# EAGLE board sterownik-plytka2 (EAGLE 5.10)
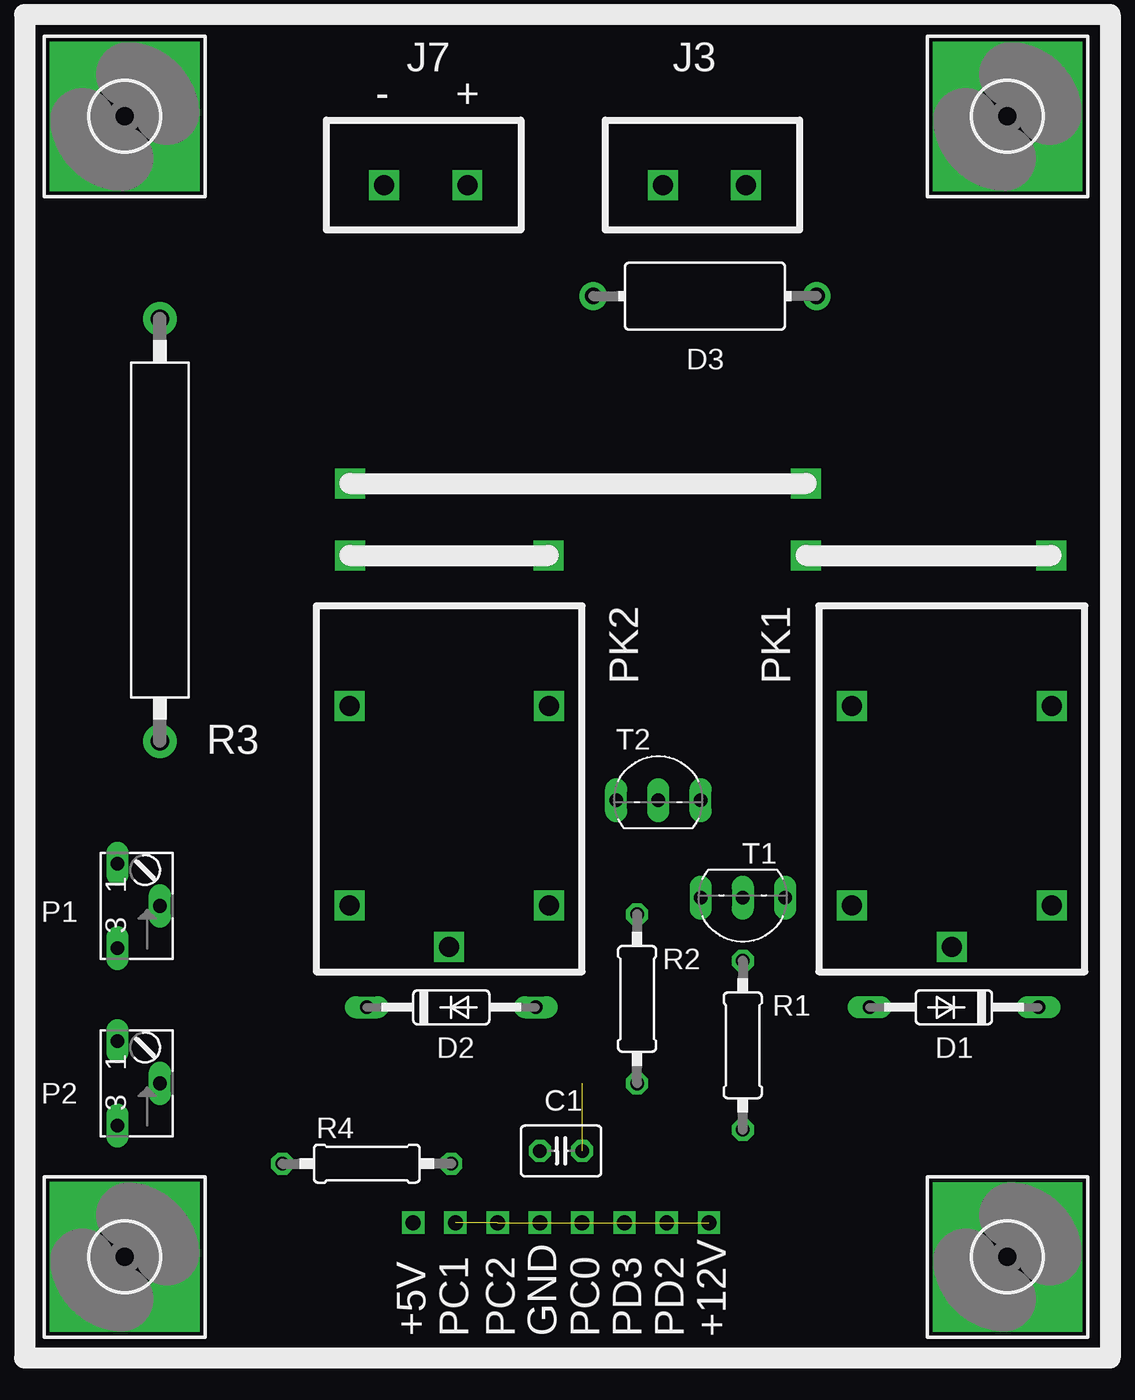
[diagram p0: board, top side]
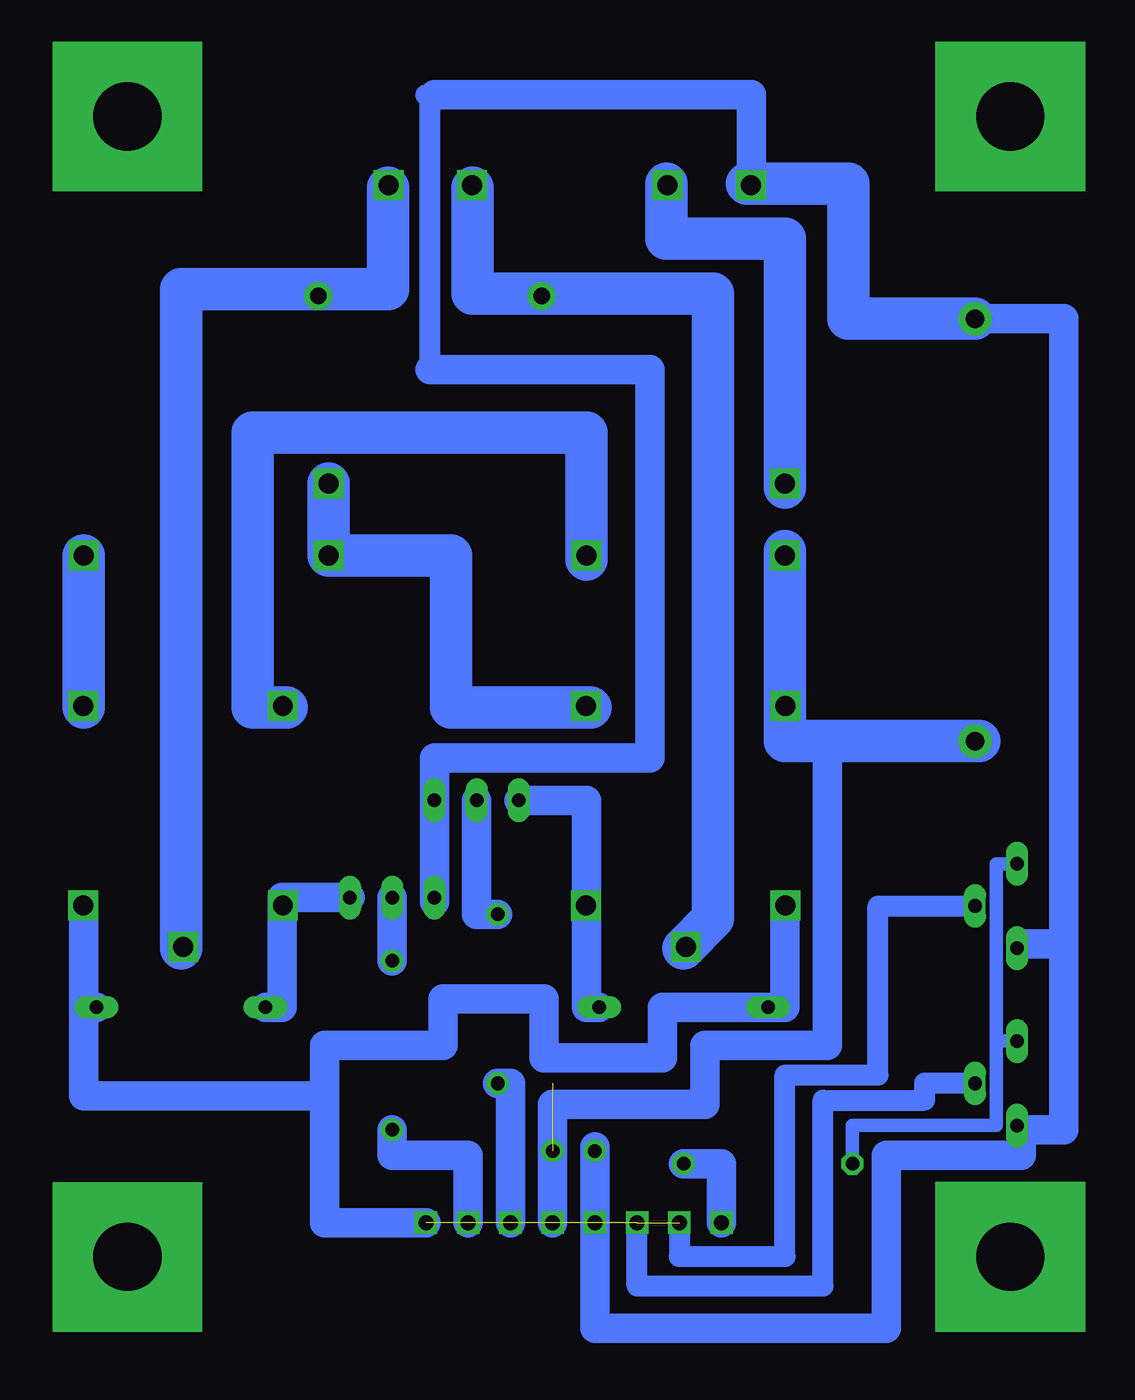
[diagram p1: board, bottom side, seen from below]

No outline drawn. Coordinates in mm, seen from the top.
Copper layers (1*16): Top 0.035mm / dielectric 1.5mm / Bottom 0.035mm
Design rules "default": minimum track width 10mil, minimum drill 24mil, track to track 8mil, track to pad 8mil, pad to pad 8mil, via to via 8mil, smd to smd 8mil, copper to edge 40mil, drill to drill 8mil, minimum pad ring 10mil, minimum via ring 8mil, stop-mask expansion 4mil, vias tented up to drill 0mil, thermal gap 10mil

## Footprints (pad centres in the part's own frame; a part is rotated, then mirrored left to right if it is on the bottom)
C025-030X050 = drill 0.813 octagon: 1 -1.27,0; 2 1.27,0
DO35-10 = drill 0.813 long: A 5.08,0; C -5.08,0
IRF-3 = drill 1 pad 1.676 round: 1 -6.705,0; 2 6.73,0
4,1-PAD-SQUARE = drill 4.1 pad 9 square: B4,1 0,0
B64W = drill 0.813 long: A 2.54,0; E -2.54,0; S 0,-2.54
0207/10 = drill 0.813 octagon: 1 -5.08,0; 2 5.08,0
CA4080 = drill 1.1 pad 2 round: 1 -12.7,0; 2 12.7,0
TO92-BCE = drill 0.813 long: B -2.54,0; C 0,0; E 2.54,0

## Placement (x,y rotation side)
C1  [C025-030X050]  32.51,12.7 180 top
D1  [DO35-10]  56.13,21.34 180 top
D2  [DO35-10]  25.91,21.34 0 top
D3  [IRF-3]  41.15,64.11 0 top
E$1  [4,1-PAD-SQUARE]  6.27,6.33 0 top
E$14  [4,1-PAD-SQUARE]  6.27,74.91 0 top
E$55  [4,1-PAD-SQUARE]  59.35,6.33 0 top
E$60  [4,1-PAD-SQUARE]  59.35,74.91 0 top
P1  [B64W]  5.84,27.43 90 top
P2  [B64W]  5.84,16.76 90 top
R1  [0207/10]  43.43,19.05 270 top
R2  [0207/10]  37.08,21.84 270 top
R3  [CA4080]  8.38,50.04 270 top
R4  [0207/10]  20.83,11.94 0 top
T1  [TO92-BCE]  43.43,27.94 180 top
T2  [TO92-BCE]  38.35,33.78 0 top

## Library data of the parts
C1 D3 R1 R2 R4 = rcl
D1 D2 = diode
E$1 E$14 E$55 E$60 = holes
P1 P2 = pot
R3 = resistor-power
T1 T2 = transistor

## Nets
S$1: T2.E
S$3: C1.1
S$4: R1.2
S$5: R2.2
S$6: P2.S
S$7: R3.1
S$8: D1.C D2.C P1.S
S$9: R4.1
S$10: P1.A P2.A
S$125: D2.A T2.B
S$126: D1.A T1.B
S$129: R2.1 T2.C
S$130: R1.1 T1.C
S$149: R4.2

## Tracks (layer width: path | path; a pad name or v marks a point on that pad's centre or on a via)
S$1
  Bottom 1.27: 41.4,76.2 41.15,76.2 41.15,59.69
  Bottom 1.778: 41.15,59.69 27.94,59.69 27.94,36.32 40.89,36.32 T2.E 40.89,27.69
S$2
  Bottom 1.778: 3.05,25.15 5.59,25.15 | 3.05,25.15 3.05,35.56 | 3.05,14.22 3.05,25.15
S$3  (1 unrouted)
S$4
  Bottom 1.778: R1.2 43.43,12.45 38.86,12.45 38.86,8.38
S$5
  Bottom 1.778: R2.2 36.32,16.76 36.32,8.38
S$6
  Bottom 1.27: P2.S 11.43,16.76 11.43,15.75
S$7
  Bottom 1.778: 40.89,76.2 21.84,76.2 21.84,70.87 | 16,62.74 16.26,62.74 | R3.1 3.05,62.74 3.05,34.29
  Bottom 2.54: 22.1,70.87 21.84,70.87 16,70.87 16,62.74 R3.1
S$8  (via drill 0.9)  (6 unrouted)
  Bottom 1.27: P1.S 14.22,27.43 14.22,17.27 19.81,17.27 19.81,6.35 26.16,6.35 v26.16,8.38 | v28.7,8.38 28.7,4.57 17.53,4.57 17.53,15.75 11.43,15.75
  Bottom 1.778: 19.81,27.43 19.81,21.34 D2.C 27.18,21.34 27.18,18.29 34.29,18.29 34.29,21.84 40.39,21.84 40.39,19.05 47.5,19.05 47.5,16 | 61.98,21.34 D1.C | 61.98,21.34 61.98,27.43 | 61.98,21.34 61.98,16 47.5,16 | 47.5,16 47.5,8.38 v41.4,8.38 | 17.27,37.34 17.27,19.05 24.64,19.05 24.64,15.49 33.78,15.49 v33.78,8.38 | 31.24,12.95 v31.24,8.38 31.24,2.03 13.72,2.03 13.72,3.56
  Bottom 2.54: 19.81,48.77 19.81,37.34 17.27,37.34 8.13,37.34
  other vias: 38.86,8.38 36.32,8.38
S$9
  Bottom 0.813: R4.1 15.75,14.22 7.11,14.22
S$10
  Bottom 0.813: P1.A 7.11,29.97 7.11,19.3 | 7.11,19.3 7.11,14.22 | P2.A 7.11,19.3
S$11
  Bottom 2.54: 25.91,24.89 24.13,26.67 24.13,64.26 25.91,64.26 26.92,64.26 38.61,64.26 38.61,70.61
S$12
  Bottom 1.778: 3.05,13.97 5.59,13.97 5.59,12.45 13.72,12.45 13.72,3.81
S$99  (via drill 1.2)
  other vias: 19.78,27.47
S$100  (via drill 1.2)
  other vias: 31.78,27.47
S$101  (via drill 1.2)
  other vias: 25.78,24.97
S$102  (via drill 1.2)
  other vias: 19.78,39.47
S$103  (via drill 1.2)
  other vias: 31.78,39.47
S$104  (via drill 1.2)
  other vias: 50.01,27.47
S$105  (via drill 1.2)
  other vias: 62.01,27.47
S$106  (via drill 1.2)
  other vias: 56.01,24.97
S$107  (via drill 1.2)
  other vias: 50.01,39.47
S$108  (via drill 1.2)
  other vias: 62.01,39.47
S$109  (via drill 1.2)
  other vias: 38.64,70.77
S$110  (via drill 1.2)
  other vias: 43.64,70.77
S$111
  Bottom 2.54: 43.69,70.61 43.69,64.52 56.13,64.52 56.13,24.89
S$112  (via drill 1.2)
  Bottom 2.54: 61.98,39.37 v61.98,48.51
S$114  (via drill 1.2)
  other vias: 31.75,48.51
S$115  (via drill 1.2)
  other vias: 19.81,48.51
S$116
  Bottom 2.54: 49.78,39.37 51.82,39.37 51.82,55.88 31.75,55.88 31.75,48.26
S$118  (via drill 1.2)
  other vias: 21.87,70.77
S$119  (via drill 1.2)
  other vias: 26.87,70.77
S$120  (via drill 1.2)
  Bottom 2.54: 31.5,39.37 39.88,39.37 39.88,48.51 v47.24,48.51 v47.24,52.83
S$121  (via drill 1.2)
  other vias: 19.81,52.83
S$123
  Bottom 2.54: 26.92,70.87 26.92,67.56 19.81,67.56 19.81,52.58
S$125
  Bottom 1.778: D2.A 31.75,21.34 31.75,33.78 T2.B
S$126
  Bottom 1.778: D1.A 50.04,21.34 50.04,27.94 T1.B
S$129
  Bottom 1.778: T2.C 38.35,26.92 R2.1
S$130
  Bottom 1.778: R1.1 T1.C
S$149  (via drill 0.9)
  Bottom 1.778: R4.2 23.62,11.94 v23.62,8.38

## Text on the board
tNames: J7 | J3 | - | + | PK2 | PK1 | +5V | PC1 | PC2 | GND | PC0 | PD3 | PD2 | +12V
